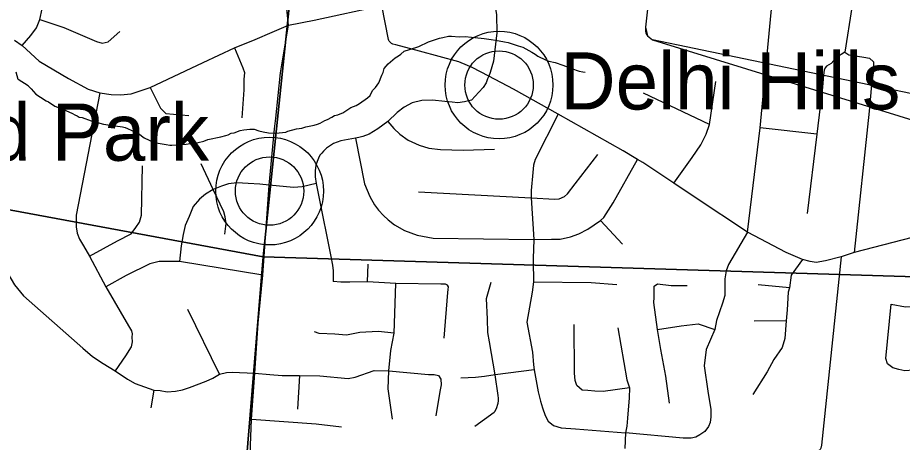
# Model space of a CAD drawing. Extents: x 0 to 34, y -2 to 22.
# Drawn here: x 4.698 to 5.919, y 15.454 to 16.041 of the extents above; entities that cross this region are included whole.
import ezdxf

# ---------------------------------------------------------------- set-up
doc = ezdxf.new("R2010")
doc.units = 0
for name, color, linetype in [('GM_X_County_Road', 7, 'Continuous'), ('GM_X_Minor_River', 7, 'Continuous'), ('GM_X_Section', 7, 'Continuous'), ('GM_X_Township_Road', 7, 'Continuous'), ('GM_X_Unincorporated', 7, 'Continuous'), ('GM_X_Unincorporated_Location', 7, 'Continuous'), ('GM_X_Unincorporated_Text', 7, 'Continuous'), ('SH_Data', 7, 'Continuous'), ('SH_Text', 7, 'Continuous')]:
    doc.layers.add(name, color=color, linetype=linetype)

msp = doc.modelspace()

# ---------------------------------------------------------------- linework, layer by layer
at = {"layer": 'GM_X_County_Road'}
msp.add_line((5.0621, 15.9758), (5.0715, 16.0307), dxfattribs=at)
for points in [[(5.0285, 16.0123), (5.0457, 16.0195), (5.0715, 16.0307), (5.1068, 16.0374), (5.2004, 16.0579), (5.3517, 16.0882), (5.4284, 16.1035), (5.4467, 16.1064), (5.4725, 16.1091), (5.512, 16.1143), (5.5739, 16.1159), (5.6997, 16.1172), (5.7116, 16.111), (5.7142, 16.1106), (5.7294, 16.1063), (5.734, 16.1047)], [(5.7054, 15.7447), (5.7226, 15.8889), (5.7432, 16.1015)], [(5.0715, 16.0307), (5.0692, 16.0529), (5.07, 16.0607)], [(5.9326, 15.7375), (5.8528, 15.7168), (5.8345, 15.7105), (5.813, 15.705), (5.8003, 15.7027), (5.7919, 15.704), (5.7813, 15.7071), (5.7586, 15.7165), (5.7054, 15.7447), (5.6332, 15.7924), (5.6037, 15.8122), (5.5606, 15.841), (5.5535, 15.8448), (5.5509, 15.8462), (5.5338, 15.8572), (5.4439, 15.9075), (5.3823, 15.942), (5.3479, 15.9601), (5.3252, 15.972), (5.3188, 15.9748), (5.3069, 15.9797), (5.2524, 15.9948), (5.2196, 16.0032), (5.2155, 16.0041), (5.2139, 16.005), (5.2122, 16.0064), (5.2107, 16.0084), (5.2101, 16.0095), (5.2096, 16.0107), (5.2004, 16.0579)], [(4.6931, 16.0098), (4.7038, 16.0026), (4.7273, 15.9806), (4.7675, 15.9567), (4.7947, 15.9423), (4.8111, 15.9371), (4.8265, 15.9347), (4.8393, 15.9343), (4.8541, 15.9357), (4.8806, 15.9445), (4.9535, 15.979), (4.9967, 15.9991), (5.0253, 16.0109), (5.0285, 16.0123)], [(5.0538, 15.902), (5.0603, 15.9649), (5.0621, 15.9758)], [(5.0176, 15.4139), (5.0202, 15.4862), (5.0248, 15.55), (5.0296, 15.6189), (5.036, 15.6855), (5.0448, 15.8098), (5.0508, 15.8726), (5.0523, 15.8872), (5.0538, 15.902)]]:
    msp.add_lwpolyline(points, dxfattribs=at)
at = {"layer": 'GM_X_Minor_River'}
for points in [[(4.7119, 15.9467), (4.716, 15.9427), (4.7226, 15.9353), (4.729, 15.9313), (4.7368, 15.9262), (4.7402, 15.9246), (4.7488, 15.9186), (4.7601, 15.9145), (4.7732, 15.9084), (4.7766, 15.9068), (4.7796, 15.9055), (4.7826, 15.9036), (4.7864, 15.9031), (4.7992, 15.8985), (4.8075, 15.8964), (4.8109, 15.8952), (4.8162, 15.8939), (4.8253, 15.8925), (4.8423, 15.8901), (4.8461, 15.8892), (4.8491, 15.888), (4.8611, 15.8823), (4.8656, 15.8799), (4.8686, 15.8779), (4.872, 15.8748), (4.8791, 15.8715), (4.8851, 15.8691), (4.8915, 15.8678), (4.9025, 15.8656), (4.9074, 15.865), (4.9105, 15.8649), (4.9189, 15.8655), (4.9303, 15.8663), (4.941, 15.8679), (4.9467, 15.8685), (4.9544, 15.8702), (4.9601, 15.8727), (4.9781, 15.8764), (4.985, 15.8781), (4.9884, 15.8791), (4.9923, 15.8813), (4.9965, 15.882), (5.0046, 15.8852), (5.0099, 15.8862), (5.0141, 15.8864), (5.0179, 15.8871), (5.024, 15.8869), (5.0304, 15.8848), (5.0365, 15.8831), (5.044, 15.8818), (5.0539, 15.8815), (5.0676, 15.883), (5.0707, 15.8841), (5.0826, 15.8872), (5.0899, 15.8885), (5.0956, 15.8902), (5.1071, 15.8926), (5.1117, 15.8936), (5.1151, 15.8954), (5.1217, 15.899), (5.1255, 15.9005), (5.1313, 15.9033), (5.1352, 15.9059), (5.1394, 15.9069), (5.1429, 15.908), (5.1463, 15.9094), (5.1506, 15.9123), (5.1575, 15.9167), (5.1649, 15.9195), (5.1695, 15.9225), (5.1804, 15.9302), (5.1842, 15.9335), (5.1855, 15.9365), (5.1879, 15.9406), (5.1914, 15.9443), (5.1961, 15.9507), (5.2006, 15.9616), (5.2022, 15.965), (5.2035, 15.9706), (5.209, 15.9773), (5.2187, 15.9855), (5.2234, 15.9884), (5.2265, 15.9906), (5.2312, 15.9946), (5.2384, 15.9971), (5.2515, 16.0013), (5.265, 16.0074), (5.2799, 16.0127), (5.2845, 16.0137), (5.2926, 16.0154), (5.2967, 16.0153), (5.307, 16.0146), (5.3154, 16.0147), (5.3241, 16.0141), (5.3374, 16.0126), (5.3419, 16.0121), (5.3514, 16.0107), (5.3574, 16.0098), (5.3696, 16.0075), (5.3749, 16.0066), (5.3846, 16.0033)], [(5.3846, 16.0033), (5.3884, 16.002), (5.3952, 16.0003), (5.4076, 15.9931), (5.4121, 15.9903), (5.4158, 15.9879), (5.4263, 15.9827), (5.4312, 15.981), (5.4395, 15.9789), (5.4501, 15.9752), (5.4598, 15.9715), (5.47, 15.9678), (5.473, 15.9669), (5.478, 15.966), (5.481, 15.9656)], [(4.7119, 15.9467), (4.6981, 15.9556), (4.6953, 15.9655)]]:
    msp.add_lwpolyline(points, dxfattribs=at)
at = {"layer": 'GM_X_Section'}
for points in [[(5.1427, 16.732), (5.0363, 15.7105), (4.012, 15.9002), (4.1192, 16.9159)], [(6.1288, 16.703), (6.0281, 15.6802), (5.0363, 15.7105), (5.1427, 16.732)]]:
    msp.add_lwpolyline(points, close=True, dxfattribs=at)
for points in [[(4.012, 15.9002), (5.0363, 15.7105), (4.955, 14.7206)], [(4.955, 14.7206), (5.0363, 15.7105), (6.0281, 15.6802), (5.9259, 14.7378), (5.9239, 14.7337)]]:
    msp.add_lwpolyline(points, dxfattribs=at)
at = {"layer": 'GM_X_Township_Road'}
for p, q in [((5.6529, 15.8932), (5.5618, 15.9365)), ((5.801, 15.8802), (5.7226, 15.8889)), ((5.5023, 15.7609), (5.5327, 15.728)), ((5.1808, 15.676), (5.1813, 15.7004)), ((5.7632, 15.6678), (5.7201, 15.6718)), ((4.976, 15.5486), (4.9327, 15.6378)), ((5.7586, 15.6223), (5.7146, 15.6219)), ((5.0868, 15.5468), (5.0839, 15.5001)), ((4.8854, 15.5263), (4.8813, 15.5022))]:
    msp.add_line(p, q, dxfattribs=at)
for points in [[(4.7038, 16.0026), (4.7159, 16.0165), (4.7237, 16.0268), (4.728, 16.0386), (4.7315, 16.0532), (4.7333, 16.0727), (4.7481, 16.2124), (4.7513, 16.2323), (4.757, 16.2512), (4.763, 16.2633), (4.7862, 16.2871), (4.7989, 16.2992), (4.8026, 16.3075), (4.8047, 16.3161), (4.8077, 16.3293), (4.8104, 16.3751), (4.819, 16.5174), (4.8199, 16.5274)], [(5.5739, 16.1159), (5.5645, 16.0279), (5.5645, 16.0222), (5.5648, 16.0201), (5.5655, 16.0184), (5.5662, 16.0171), (5.5672, 16.016), (5.5742, 16.0105)], [(5.3517, 16.0882), (5.3586, 16.0447), (5.3594, 16.02), (5.3546, 15.9807), (5.3498, 15.9651), (5.3479, 15.9601)], [(5.8492, 16.0548), (5.8398, 15.9932), (5.8283, 15.986), (5.8209, 15.9778), (5.8145, 15.9738), (5.8127, 15.9717), (5.8113, 15.9686), (5.8103, 15.9614), (5.8088, 15.9448), (5.801, 15.8802), (5.7878, 15.7705)], [(4.728, 16.0386), (4.7611, 16.0274), (4.8064, 16.0078), (4.8143, 16.0055), (4.8226, 16.0073), (4.8388, 16.022)], [(4.9967, 15.9991), (5.0082, 15.9718), (5.0106, 15.9654), (5.0097, 15.9553), (5.0097, 15.9413), (5.0072, 15.9026)], [(5.8398, 15.9932), (5.8453, 15.9896), (5.866, 15.9863), (5.8737, 15.9849), (5.8792, 15.98), (5.8792, 15.9742), (5.8792, 15.9668), (5.8784, 15.9615), (5.8767, 15.9483), (5.8731, 15.9117), (5.8528, 15.7168)], [(5.3479, 15.9601), (5.3465, 15.9566), (5.3443, 15.951), (5.3401, 15.9444), (5.3345, 15.938), (5.3244, 15.9272), (5.3144, 15.9247), (5.3052, 15.9231), (5.2973, 15.924), (5.2874, 15.925), (5.2702, 15.9269), (5.2558, 15.9266), (5.2421, 15.9231), (5.2311, 15.9173), (5.2215, 15.9099), (5.2087, 15.8973), (5.195, 15.8874), (5.1827, 15.8798), (5.174, 15.8766), (5.1686, 15.8752), (5.1638, 15.8743), (5.1438, 15.8707), (5.1336, 15.8673), (5.1239, 15.8609), (5.1199, 15.8566)], [(4.8806, 15.9445), (4.8949, 15.916), (4.9023, 15.9085), (4.934, 15.9057)], [(5.6037, 15.8122), (5.629, 15.8479), (5.6409, 15.8655), (5.6484, 15.88), (5.6529, 15.8932), (5.6616, 15.9527)], [(4.8111, 15.9371), (4.7781, 15.768), (4.7782, 15.7591), (4.7781, 15.752), (4.7797, 15.7434), (4.7829, 15.7352), (4.7883, 15.7258), (4.7968, 15.7117), (4.8192, 15.6694), (4.8507, 15.6153), (4.8545, 15.6085), (4.8554, 15.6043), (4.8552, 15.5996), (4.8554, 15.5932), (4.8541, 15.5861), (4.8463, 15.5738), (4.8322, 15.553)], [(5.4439, 15.9075), (5.4119, 15.8449), (5.4098, 15.8374), (5.4088, 15.8272), (5.4066, 15.8022), (5.4064, 15.7921), (5.4101, 15.7344), (5.4093, 15.7081), (5.4093, 15.7052)], [(5.2087, 15.8973), (5.217, 15.8879), (5.225, 15.88), (5.2368, 15.8715), (5.252, 15.865), (5.2655, 15.8605), (5.2814, 15.859), (5.3125, 15.858), (5.3559, 15.8593)], [(5.1638, 15.8743), (5.1763, 15.8112), (5.1839, 15.7941), (5.1902, 15.7826), (5.1957, 15.7749), (5.2027, 15.7679), (5.2093, 15.7618), (5.218, 15.7549), (5.2317, 15.7469), (5.2492, 15.7406), (5.2712, 15.7364), (5.4101, 15.7344), (5.4347, 15.7348), (5.4464, 15.735), (5.4609, 15.7384), (5.4723, 15.7422), (5.4848, 15.7488), (5.5023, 15.7609), (5.5067, 15.765), (5.5198, 15.7852), (5.5535, 15.8448)], [(5.1199, 15.8566), (5.1173, 15.8538), (5.1148, 15.851), (5.1127, 15.847), (5.111, 15.8424), (5.1092, 15.8373), (5.1081, 15.8295), (5.1082, 15.8209), (5.1095, 15.8119)], [(5.2509, 15.8006), (5.4064, 15.7921), (5.4392, 15.7903), (5.4453, 15.7909), (5.4526, 15.7941), (5.4569, 15.7974), (5.4674, 15.8112), (5.4985, 15.8519)], [(4.7968, 15.7117), (4.8354, 15.7329), (4.8542, 15.7423), (4.8605, 15.7509), (4.8657, 15.7585), (4.8685, 15.7681), (4.8701, 15.8361)], [(4.9836, 15.742), (4.9854, 15.7566), (4.9842, 15.766), (4.982, 15.7726), (4.9675, 15.8035), (4.9511, 15.839)], [(5.1095, 15.8119), (5.0902, 15.8074), (5.0786, 15.8062), (5.0448, 15.8098), (5.0319, 15.8108), (5.0157, 15.8119), (5, 15.8126), (4.9885, 15.8112), (4.9788, 15.8084), (4.9675, 15.8035), (4.9568, 15.7973), (4.9488, 15.7902), (4.9399, 15.7801), (4.9342, 15.7665), (4.9286, 15.7541), (4.9262, 15.7416), (4.9233, 15.726), (4.9208, 15.7043)], [(5.1095, 15.8119), (5.1127, 15.7959), (5.1301, 15.7113), (5.1324, 15.6992), (5.1331, 15.6915), (5.1332, 15.6766)], [(4.6459, 15.7784), (4.644, 15.7655), (4.6458, 15.7571), (4.6484, 15.7489), (4.655, 15.7361), (4.6929, 15.6721), (4.7055, 15.6568), (4.7876, 15.5843), (4.8007, 15.5731), (4.8157, 15.5635), (4.8322, 15.553), (4.8491, 15.5416), (4.8598, 15.5358), (4.8854, 15.5263), (4.8943, 15.5258), (4.9038, 15.5244), (4.9155, 15.5249), (4.9249, 15.5271), (4.9347, 15.5301), (4.9577, 15.539), (4.9669, 15.5432), (4.976, 15.5486)], [(5.7054, 15.7447), (5.6792, 15.6998), (5.6759, 15.6912), (5.6741, 15.6802), (5.6738, 15.6571), (5.6709, 15.6465), (5.6627, 15.6229), (5.66, 15.6101), (5.6481, 15.5826), (5.6454, 15.5599), (5.6505, 15.5249), (5.6545, 15.4997), (5.6549, 15.4895), (5.6537, 15.4819), (5.6515, 15.4764), (5.6465, 15.4696), (5.6395, 15.4647), (5.6339, 15.4615), (5.6274, 15.46), (5.6165, 15.4601), (5.537, 15.4677)], [(5.8345, 15.7105), (5.8077, 15.4503), (5.8064, 15.4465), (5.8055, 15.4446), (5.8044, 15.4432), (5.7928, 15.4336)], [(5.036, 15.6855), (4.9208, 15.7043), (4.9027, 15.7041), (4.8929, 15.7041), (4.8799, 15.7009), (4.8472, 15.6849), (4.8192, 15.6694)], [(5.4093, 15.7052), (5.4096, 15.6762), (5.408, 15.6618), (5.4008, 15.6202), (5.4082, 15.5788), (5.41, 15.5613), (5.4107, 15.5545), (5.4163, 15.5241), (5.4195, 15.5114), (5.4221, 15.5023), (5.4259, 15.4917), (5.4301, 15.4836), (5.4373, 15.4775), (5.4479, 15.4743), (5.4677, 15.473), (5.537, 15.4677)], [(5.7813, 15.7071), (5.7657, 15.6851), (5.7632, 15.6678), (5.7614, 15.662), (5.7601, 15.6374), (5.7586, 15.6223), (5.757, 15.5977), (5.7531, 15.5856), (5.7419, 15.5689), (5.7324, 15.5519), (5.7126, 15.5207)], [(5.2866, 15.5984), (5.2914, 15.6615), (5.2921, 15.6657), (5.2924, 15.6691), (5.291, 15.6714), (5.2881, 15.6727), (5.2818, 15.673), (5.2197, 15.674), (5.1808, 15.676), (5.156, 15.6755), (5.1437, 15.6755), (5.1332, 15.6766)], [(5.2151, 15.4864), (5.2092, 15.5285), (5.2101, 15.5533), (5.2128, 15.5811), (5.2173, 15.6053), (5.2197, 15.674)], [(5.3286, 15.4769), (5.3555, 15.496), (5.3565, 15.497), (5.3588, 15.5011), (5.3609, 15.5086), (5.3613, 15.5116), (5.3613, 15.5155), (5.3608, 15.5189), (5.3569, 15.5477), (5.3489, 15.5933), (5.3467, 15.6062), (5.3463, 15.6244), (5.3451, 15.6531), (5.3512, 15.6758)], [(5.4096, 15.6762), (5.4895, 15.6753), (5.5247, 15.6722)], [(5.5976, 15.5085), (5.5924, 15.5459), (5.5856, 15.5826), (5.5811, 15.6102), (5.5759, 15.6475), (5.5765, 15.6543), (5.5762, 15.67), (5.5811, 15.6734), (5.6, 15.6711), (5.6219, 15.6711)], [(5.934, 15.554), (5.9224, 15.5531), (5.9144, 15.5551), (5.9059, 15.5573), (5.8987, 15.563), (5.8964, 15.5704), (5.9037, 15.6451), (5.9235, 15.6417), (5.9692, 15.6433)], [(5.5423, 15.5298), (5.5062, 15.5247), (5.4946, 15.5252), (5.485, 15.5258), (5.4769, 15.5265), (5.4698, 15.5328), (5.4674, 15.54), (5.4665, 15.5499), (5.466, 15.6171)], [(5.5261, 15.6124), (5.5387, 15.5407), (5.5423, 15.5298), (5.5419, 15.5158), (5.5396, 15.488), (5.5385, 15.4766), (5.537, 15.4677), (5.5358, 15.4458)], [(5.5811, 15.6102), (5.6136, 15.6155), (5.6371, 15.6181), (5.66, 15.6101)], [(5.2173, 15.6053), (5.1951, 15.6074), (5.1699, 15.6062), (5.1517, 15.6023), (5.1356, 15.6036), (5.1139, 15.6046), (5.1072, 15.6071)], [(4.976, 15.5486), (4.9858, 15.5511), (4.9936, 15.5514), (5.0039, 15.5511), (5.0248, 15.55)], [(5.0248, 15.55), (5.0459, 15.5482), (5.0628, 15.5466), (5.0868, 15.5468), (5.1146, 15.5461), (5.1541, 15.5425), (5.1634, 15.5442), (5.1897, 15.5535), (5.2101, 15.5533), (5.2648, 15.548), (5.2728, 15.5482), (5.2786, 15.5469), (5.2819, 15.5416), (5.2824, 15.534), (5.2803, 15.5248), (5.2748, 15.4911)], [(5.4107, 15.5545), (5.3569, 15.5477), (5.3421, 15.5455), (5.3298, 15.544), (5.3096, 15.543)], [(5.0202, 15.4862), (5.1098, 15.4798), (5.1448, 15.4757)]]:
    msp.add_lwpolyline(points, dxfattribs=at)
at = {"layer": 'GM_X_Unincorporated'}
for centre, radius in [((5.3622, 15.9479), 0.0744), ((5.3622, 15.9479), 0.0472), ((5.0454, 15.8014), 0.0744), ((5.0454, 15.8014), 0.0472)]:
    msp.add_circle(centre, radius, dxfattribs=at)
at = {"layer": 'GM_X_Unincorporated_Location'}
for p, q in [((5.3622, 15.9479), (5.3622, 15.9479)), ((5.0454, 15.8014), (5.0454, 15.8014))]:
    msp.add_line(p, q, dxfattribs=at)
at = {"layer": 'SH_Data'}
msp.add_lwpolyline([(5.5742, 16.0105), (9.9214, 14.669), (9.9247, 15.1051)], close=True, dxfattribs=at)
at = {"layer": 'SH_Text'}
msp.add_lwpolyline([(5.5739, 16.1159), (5.5645, 16.0279), (5.5672, 16.016), (5.5742, 16.0105)], dxfattribs=at)

# ---------------------------------------------------------------- texts
at = {"layer": 'GM_X_Unincorporated_Text'}
for s, p in [('Delhi Hills', (5.4469, 15.9141)), ('Highland Park', (4.2985, 15.8433))]:
    msp.add_text(s, height=0.078977, rotation=0, dxfattribs=at).set_placement(p)

doc.saveas('drawing.dxf')
